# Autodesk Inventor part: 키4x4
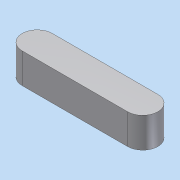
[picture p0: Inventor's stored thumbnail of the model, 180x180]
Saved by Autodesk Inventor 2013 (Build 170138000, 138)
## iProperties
Company: 한국ATC센터
Created: 2009-02
Part Number: 키4x4
Document SubType Name: Modeling
Designer: KYOUNG IL JANG
Density: 1 g/cm^3
Mass: 0.274265 g
Surface Area: 2.99398 cm^2
Volume: 0.274265 cm^3
Vendor: CBT Solutions
Material: 일반
Author: KYOUNG IL JANG
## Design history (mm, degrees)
sketch "스케치1"
  geometry: L1 (0, 2)-(14, 2); L2 (0, -2)-(14, -2); A1 r 2 centre (0, 0) between (0, 2) and (0, -2); A2 r 2 centre (14, 0) between (14, -2) and (14, 2); 1 further point
  constraints: 4 end point, 4 point on circle, 3 tangent, 2 centre point, 1 coincident, 1 equal radius, 1 horizontal alignment, 1 parallel
  dimensions: "d0" = 4 distance between parallel lines of L2 L1; "d1" = 18 dimension on A2 A1
extrude "돌출1" new body sketch "스케치1" distance "d2" = 4; taper "d3" = 0 deg
node "솔리드1"
